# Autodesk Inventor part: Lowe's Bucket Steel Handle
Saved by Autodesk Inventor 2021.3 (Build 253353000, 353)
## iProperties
Created: 2022-12
Part Number: Lowe's Bucket Steel Handle
Material: Generic
Document SubType Name: Modeling
Designer: AdminForWorker
Density: 1 g/cm^3
Appearance: Default
Title: Lowe's Bucket Steel Handle
Author: AdminForWorker
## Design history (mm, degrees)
feature "Body1"
body "Solid1"
